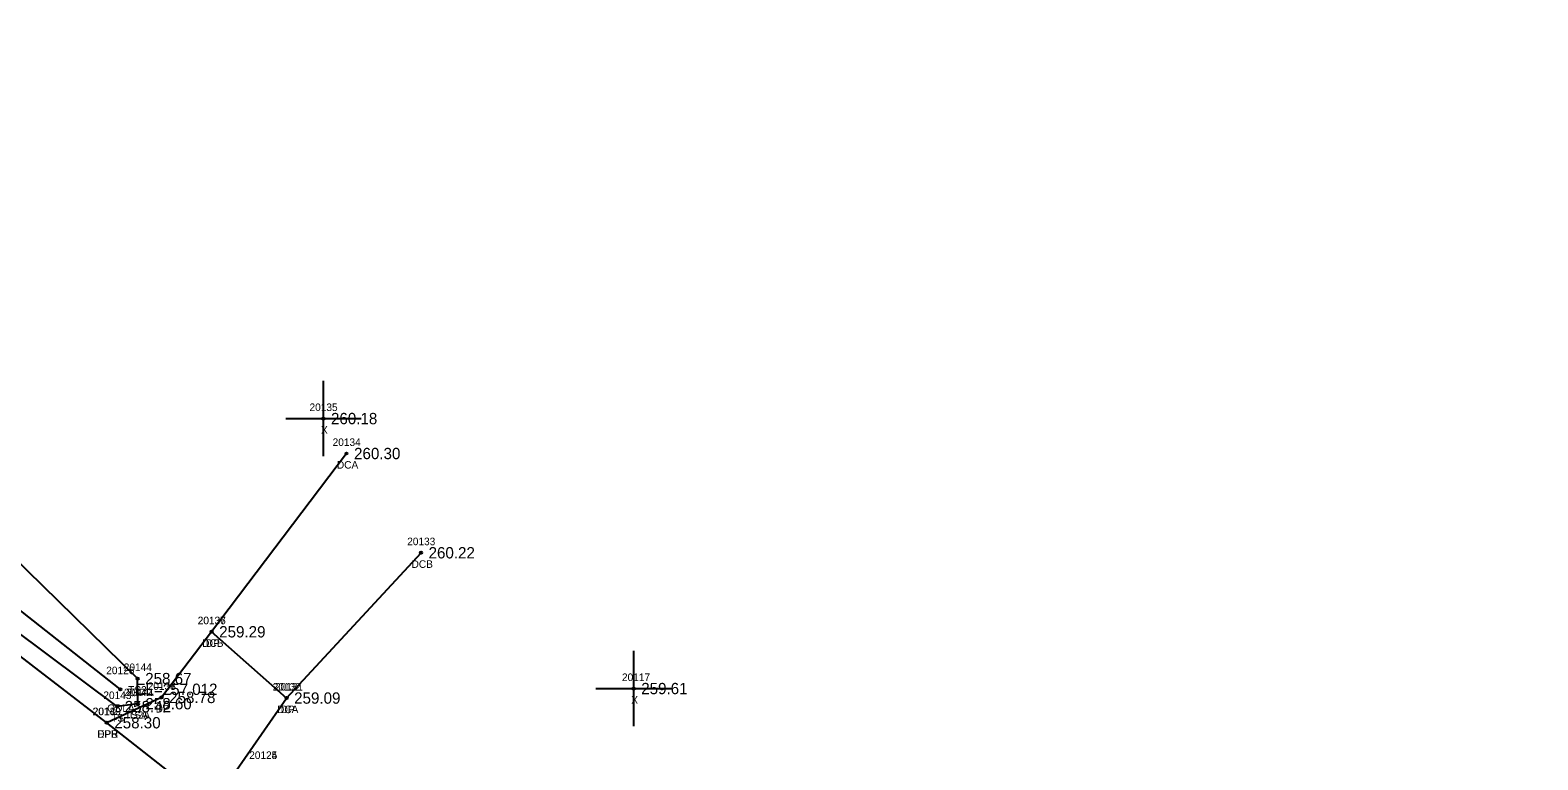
# Model space of a CAD drawing. Extents: x 1961330 to 1962287, y 800294 to 801079.
# Drawn here: x 1961887.6 to 1962087.3, y 800631.3 to 800727.9 of the extents above; entities that cross this region are included whole.
import ezdxf

# ---------------------------------------------------------------- set-up
doc = ezdxf.new("R2010")
doc.units = 0
for name, color, linetype in [('RD_DTM_BkLn2', 7, 'Continuous'), ('RD_DTM_BkLn_txCode', 7, 'Continuous'), ('RD_EX_Conc', 7, 'Continuous'), ('RD_EX_Conc_txCode', 7, 'Continuous'), ('RD_EX_Driveway', 7, 'Continuous'), ('RD_EX_Driveway_txCode', 7, 'Continuous'), ('RD_EX_H2O', 7, 'Continuous'), ('RD_EX_H2O_txCode', 7, 'Continuous'), ('RD_EX_Misc', 7, 'Continuous'), ('RD_EX_Misc_txCode', 7, 'Continuous'), ('RD_EX_Road', 7, 'Continuous'), ('RD_EX_Road_txCode', 7, 'Continuous'), ('RD_EX_TX_Conc_ELEV', 7, 'Continuous'), ('RD_EX_TX_Driveway_ELEV', 7, 'Continuous'), ('RD_EX_TX_H2O_ELEV', 7, 'Continuous'), ('RD_EX_TX_Misc_ELEV', 7, 'Continuous'), ('RD_EX_TX_Road_ELEV', 7, 'Continuous'), ('RD_SMD_Locator', 7, 'Continuous')]:
    doc.layers.add(name, color=color, linetype=linetype)

msp = doc.modelspace()

# ---------------------------------------------------------------- linework, layer by layer
at = {"layer": 'RD_DTM_BkLn2'}
for points in [[(1961901.85, 800638.69), (1961901.82, 800642.02), (1961859.99, 800682.92), (1961825.68, 800711.98), (1961798, 800725.18), (1961794.11, 800724.28), (1961795.5, 800718.8)], [(1961901.85, 800638.69), (1961899.11, 800638.31), (1961852.87, 800672.87), (1961817.37, 800700.53), (1961795.5, 800718.8)]]:
    msp.add_lwpolyline(points, dxfattribs=at)
at = {"layer": 'RD_EX_Conc'}
for p, q in [((1961929.49, 800671.84), (1961911.62, 800648.22)), ((1961921.55, 800639.44), (1961939.36, 800658.69))]:
    msp.add_line(p, q, dxfattribs=at)
at = {"layer": 'RD_EX_Driveway'}
msp.add_lwpolyline([(1961913.43, 800623.83), (1961913.8, 800628.31), (1961921.55, 800639.44), (1961911.62, 800648.22), (1961904.99, 800639.52), (1961897.73, 800636.17)], dxfattribs=at)
at = {"layer": 'RD_EX_H2O'}
msp.add_lwpolyline([(1961899.52, 800640.6), (1961855.45, 800675.35), (1961819.11, 800703.44), (1961797.7, 800721.16)], dxfattribs=at)
at = {"layer": 'RD_EX_Misc'}
for p, q in [((1961926.43, 800671.47), (1961926.43, 800681.47)), ((1961921.43, 800676.47), (1961931.43, 800676.47)), ((1961967.53, 800635.7), (1961967.53, 800645.7)), ((1961962.53, 800640.7), (1961972.53, 800640.7))]:
    msp.add_line(p, q, dxfattribs=at)
at = {"layer": 'RD_EX_Road'}
msp.add_lwpolyline([(1962276.74, 800366.53), (1962275.76, 800367.28), (1962226.46, 800400.66), (1962183.05, 800429.73), (1962145.98, 800455.38), (1962104.4, 800484.06), (1962056.77, 800517.94), (1962023.95, 800541.05), (1961991.87, 800563.56), (1961983.89, 800569.94), (1961938.77, 800603.67), (1961913.43, 800623.83), (1961897.73, 800636.17), (1961851.62, 800671.61), (1961815.86, 800699.48), (1961795.77, 800715.49), (1961771.88, 800733.73), (1961750.77, 800750.96), (1961735.63, 800762.82), (1961702.92, 800788.52), (1961676.16, 800810.27), (1961651.45, 800830.73), (1961641.14, 800839.02)], dxfattribs=at)
at = {"layer": 'RD_SMD_Locator'}
for centre in [(1961926.43, 800676.47), (1961929.49, 800671.84), (1961939.36, 800658.69), (1961911.62, 800648.22), (1961911.62, 800648.22), (1961901.82, 800642.02), (1961967.53, 800640.7), (1961899.52, 800640.6), (1961901.85, 800638.69), (1961901.85, 800638.69), (1961904.99, 800639.52), (1961921.55, 800639.44), (1961921.55, 800639.44), (1961899.11, 800638.31), (1961897.73, 800636.17), (1961897.73, 800636.17)]:
    msp.add_circle(centre, 0.15, dxfattribs=at)

# ---------------------------------------------------------------- texts
at = {"layer": 'RD_DTM_BkLn_txCode'}
for s, p in [('20144', (1961899.98, 800643.02)), ('TS2', (1961900.57, 800640.02)), ('20143', (1961897.28, 800639.31)), ('20142', (1961900.02, 800639.69)), ('20141', (1961900.3, 800639.69)), ('TS', (1961898.32, 800636.31)), ('TS2A', (1961900.12, 800636.69)), ('TSA', (1961900.57, 800636.69)), ('20124', (1961916.6, 800631.37)), ('20125', (1961916.6, 800631.37))]:
    msp.add_text(s, height=1, dxfattribs=at).set_placement(p)
at = {"layer": 'RD_EX_Conc_txCode'}
for s, p in [('20134', (1961927.65, 800672.84)), ('DCA', (1961928.22, 800669.84)), ('20133', (1961937.53, 800659.69)), ('DCB', (1961938.11, 800656.69)), ('20136', (1961909.77, 800649.22)), ('DCB', (1961910.37, 800646.22)), ('20132', (1961919.72, 800640.44)), ('DCA', (1961920.29, 800637.44))]:
    msp.add_text(s, height=1, dxfattribs=at).set_placement(p)
at = {"layer": 'RD_EX_Driveway_txCode'}
for s, p in [('20137', (1961909.79, 800649.22)), ('DP', (1961910.84, 800646.22)), ('20138', (1961903.15, 800640.52)), ('20131', (1961920, 800640.44)), ('20139', (1961895.89, 800637.17)), ('DP', (1961904.21, 800637.52)), ('DP', (1961920.77, 800637.44)), ('DPB', (1961896.47, 800634.17))]:
    msp.add_text(s, height=1, dxfattribs=at).set_placement(p)
at = {"layer": 'RD_EX_H2O_txCode'}
for s, p in [('20126', (1961897.66, 800642.6)), ('ODLA', (1961897.79, 800637.6))]:
    msp.add_text(s, height=1, dxfattribs=at).set_placement(p)
at = {"layer": 'RD_EX_Misc_txCode'}
for s, p in [('20135', (1961924.59, 800677.47)), ('X', (1961926.11, 800674.47)), ('20117', (1961965.98, 800641.7)), ('X', (1961967.21, 800638.7))]:
    msp.add_text(s, height=1, dxfattribs=at).set_placement(p)
at = {"layer": 'RD_EX_Road_txCode'}
for s, p in [('20140', (1961895.85, 800637.17)), ('EPR', (1961896.5, 800634.17))]:
    msp.add_text(s, height=1, dxfattribs=at).set_placement(p)
at = {"layer": 'RD_EX_TX_Conc_ELEV'}
for s, p in [('260.30', (1961930.49, 800671.09)), ('260.22', (1961940.36, 800657.94)), ('259.29', (1961912.62, 800647.47)), ('259.09', (1961922.55, 800638.69))]:
    msp.add_text(s, height=1.5, dxfattribs=at).set_placement(p)
at = {"layer": 'RD_EX_TX_Driveway_ELEV'}
for s, p in [('259.29', (1961912.62, 800647.47)), ('258.78', (1961905.99, 800638.77)), ('259.09', (1961922.55, 800638.69)), ('258.30', (1961898.73, 800635.42))]:
    msp.add_text(s, height=1.5, dxfattribs=at).set_placement(p)
at = {"layer": 'RD_EX_TX_H2O_ELEV'}
msp.add_text('EL=257.012', height=1.5, dxfattribs=at).set_placement((1961901.52, 800639.85))
at = {"layer": 'RD_EX_TX_Misc_ELEV'}
for s, p in [('260.18', (1961927.43, 800675.72)), ('258.67', (1961902.82, 800641.27)), ('259.61', (1961968.53, 800639.95)), ('258.42', (1961900.11, 800637.56)), ('258.60', (1961902.85, 800637.94)), ('258.60', (1961902.85, 800637.94))]:
    msp.add_text(s, height=1.5, dxfattribs=at).set_placement(p)
at = {"layer": 'RD_EX_TX_Road_ELEV'}
msp.add_text('258.30', height=1.5, dxfattribs=at).set_placement((1961898.73, 800635.42))

doc.saveas('drawing.dxf')
